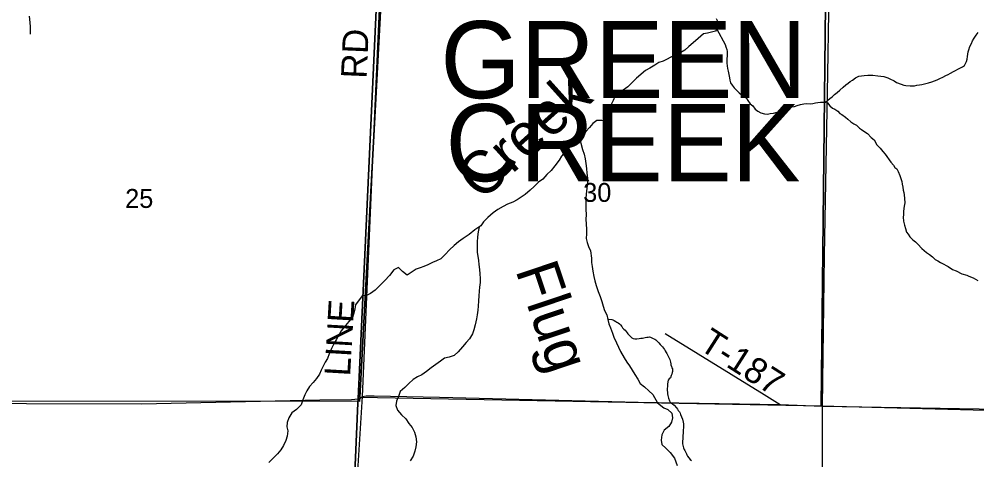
# Model space of a CAD drawing. Extents: x 36.7 to 70.7, y 0 to 22.
# Drawn here: x 40.424 to 42.544, y 14.842 to 15.816 of the extents above; entities that cross this region are included whole.
import ezdxf

# ---------------------------------------------------------------- set-up
doc = ezdxf.new("R2010")
doc.units = 0
for name, color, linetype in [('GM_X_County_Road', 7, 'Continuous'), ('GM_X_County_Road_Text', 7, 'Continuous'), ('GM_X_Minor_River', 7, 'Continuous'), ('GM_X_Minor_River_Text', 7, 'Continuous'), ('GM_X_Section', 7, 'Continuous'), ('GM_X_Section_Text', 7, 'Continuous'), ('GM_X_State_Route', 7, 'Continuous'), ('GM_X_Township_Road', 7, 'Continuous'), ('GM_X_Township_Road_Text', 7, 'Continuous'), ('GM_X_Township_Text', 7, 'Continuous')]:
    doc.layers.add(name, color=color, linetype=linetype)

msp = doc.modelspace()

# ---------------------------------------------------------------- linework, layer by layer
at = {"layer": 'GM_X_County_Road'}
for p, q in [((41.1529, 14.4774), (41.1844, 14.9819)), ((42.202, 14.9604), (42.7218, 14.9518))]:
    msp.add_line(p, q, dxfattribs=at)
for points in [[(41.1844, 14.9819), (41.2095, 15.5574), (41.2295, 16.0217), (41.2394, 16.377)], [(39.1004, 14.9709), (39.3903, 14.9674), (39.7009, 14.9673), (39.866, 14.9673), (40.1853, 14.9672), (40.6951, 14.9659), (41.0895, 14.9744), (41.1597, 14.9749), (41.1747, 14.9764), (41.1765, 14.9766), (41.1844, 14.9819)], [(41.1844, 14.9819), (41.1925, 14.983), (41.2101, 14.9829), (41.3544, 14.98), (41.7944, 14.9695), (42.1083, 14.9642), (42.202, 14.9604)]]:
    msp.add_lwpolyline(points, dxfattribs=at)
at = {"layer": 'GM_X_Minor_River'}
for points in [[(40.4461, 15.8224), (40.4479, 15.8083), (40.4489, 15.7989), (40.4487, 15.7825)], [(41.9671, 15.8174), (41.971, 15.8086), (41.9692, 15.7965), (41.9687, 15.7938), (41.9652, 15.7892)], [(41.9687, 15.7938), (41.987, 15.7599), (41.9884, 15.7549), (41.9903, 15.7488), (41.991, 15.7443), (41.9907, 15.7185), (41.991, 15.7128), (41.9917, 15.7067), (41.9931, 15.701), (41.9949, 15.6937), (41.9964, 15.6861), (41.9974, 15.6808), (41.9989, 15.6751), (42.0026, 15.6697), (42.0071, 15.664), (42.0124, 15.6582), (42.018, 15.6529), (42.0225, 15.6494), (42.0274, 15.6463), (42.033, 15.6417), (42.0368, 15.636), (42.042, 15.6287), (42.048, 15.6241), (42.0532, 15.6172), (42.0589, 15.6126), (42.066, 15.6087), (42.074, 15.6063), (42.0804, 15.6059), (42.0861, 15.6073), (42.0937, 15.6084), (42.1021, 15.6102), (42.1089, 15.612), (42.1143, 15.6146), (42.1196, 15.6168), (42.1249, 15.6183), (42.1333, 15.622), (42.1406, 15.6231), (42.1463, 15.6253), (42.1535, 15.6271), (42.1607, 15.6286), (42.1676, 15.6296), (42.1751, 15.6284), (42.1812, 15.6295), (42.1865, 15.6306), (42.1919, 15.6313), (42.1975, 15.632), (42.2036, 15.6323), (42.2086, 15.6326), (42.2139, 15.6367), (42.2185, 15.6408), (42.2235, 15.6438), (42.2288, 15.6491), (42.2346, 15.6536), (42.2403, 15.6588), (42.248, 15.6656), (42.2541, 15.6708), (42.2587, 15.6742), (42.2637, 15.6779), (42.2683, 15.6813), (42.2752, 15.6858), (42.2828, 15.6899), (42.2942, 15.6916), (42.3025, 15.6923), (42.3079, 15.6923), (42.3139, 15.6918), (42.3245, 15.6909), (42.3378, 15.6889), (42.3465, 15.6858), (42.351, 15.6838), (42.3608, 15.6795), (42.3661, 15.6757), (42.3763, 15.6725), (42.3823, 15.6702), (42.3869, 15.669), (42.396, 15.6682), (42.4009, 15.6681), (42.4062, 15.6688), (42.4112, 15.6699), (42.4169, 15.671), (42.4218, 15.6717), (42.4313, 15.6738), (42.4366, 15.6749), (42.4442, 15.6771), (42.4503, 15.6793), (42.456, 15.6816), (42.4621, 15.6845), (42.4686, 15.6875), (42.4755, 15.6912), (42.4805, 15.6934), (42.4858, 15.6964), (42.4919, 15.6998), (42.4965, 15.7024), (42.5015, 15.705), (42.506, 15.7072), (42.5118, 15.7106), (42.5167, 15.7135), (42.521, 15.7219), (42.5222, 15.7272), (42.5234, 15.7332), (42.5238, 15.7381), (42.5246, 15.7435)], [(41.9652, 15.7892), (41.9565, 15.7868), (41.9478, 15.785), (41.9387, 15.7836), (41.9268, 15.7734), (41.9157, 15.7633), (41.9065, 15.7554), (41.8977, 15.7476), (41.8885, 15.742), (41.8798, 15.739), (41.8584, 15.7271), (41.8496, 15.723), (41.8401, 15.7201), (41.8309, 15.7145), (41.8199, 15.7078), (41.8103, 15.7026), (41.7904, 15.6853), (41.7812, 15.6759), (41.7716, 15.6665), (41.7586, 15.6576), (41.7498, 15.6539), (41.7425, 15.6448), (41.7386, 15.6362), (41.7344, 15.6271), (41.732, 15.6169), (41.7317, 15.5971), (41.7222, 15.5904), (41.7135, 15.5916), (41.7029, 15.5921), (41.6937, 15.5854), (41.6864, 15.5764), (41.6787, 15.5673), (41.6706, 15.5572), (41.6614, 15.5501), (41.6507, 15.5422), (41.6407, 15.5332), (41.6338, 15.5242), (41.6242, 15.5133), (41.6195, 15.5038), (41.6099, 15.4914), (41.6015, 15.4816), (41.5922, 15.4722), (41.583, 15.4625), (41.5738, 15.4553), (41.5643, 15.446), (41.5551, 15.4381), (41.5443, 15.4279), (41.5355, 15.4227), (41.5267, 15.4164), (41.5168, 15.4115), (41.5054, 15.4067), (41.4951, 15.4015), (41.4833, 15.3948), (41.4733, 15.3881), (41.4614, 15.3776), (41.4519, 15.3682), (41.4461, 15.3588), (41.4327, 15.3502), (41.4204, 15.3401), (41.4067, 15.3311), (41.3967, 15.3236), (41.3872, 15.3154), (41.3768, 15.3056), (41.3672, 15.2959)], [(42.5246, 15.7435), (42.5258, 15.748), (42.5282, 15.7556), (42.5317, 15.762), (42.534, 15.7676), (42.5379, 15.7741), (42.5425, 15.7805), (42.5468, 15.7865)], [(42.2099, 15.6336), (42.2135, 15.631), (42.2187, 15.6241), (42.2247, 15.6191), (42.2292, 15.6172), (42.236, 15.6122), (42.2405, 15.6072), (42.245, 15.6049), (42.2529, 15.5991), (42.2582, 15.5949), (42.265, 15.5891), (42.2717, 15.5841), (42.2774, 15.5814), (42.2838, 15.5752), (42.2883, 15.5721), (42.2939, 15.5679), (42.3018, 15.5629), (42.3101, 15.5541), (42.3169, 15.5494), (42.3228, 15.538), (42.3299, 15.5307), (42.3355, 15.5234), (42.3411, 15.5177), (42.3445, 15.5119), (42.3497, 15.505), (42.3535, 15.5001), (42.3591, 15.4932), (42.3621, 15.4882), (42.3666, 15.4847), (42.3695, 15.4794), (42.3736, 15.4699), (42.3758, 15.4638), (42.378, 15.4573), (42.3787, 15.4508), (42.3801, 15.4447), (42.3808, 15.4375), (42.3823, 15.4326), (42.383, 15.4276), (42.384, 15.4193), (42.3843, 15.4101), (42.3827, 15.4022), (42.3818, 15.3912), (42.3813, 15.3836), (42.3809, 15.3779), (42.3812, 15.3692), (42.3837, 15.3608), (42.3863, 15.3528), (42.3885, 15.3452), (42.3922, 15.3406), (42.3956, 15.3345), (42.402, 15.3279), (42.408, 15.3233), (42.4136, 15.3183), (42.4218, 15.3088), (42.4327, 15.2999), (42.4391, 15.2953), (42.4459, 15.2907), (42.4515, 15.2849), (42.4572, 15.2814), (42.4636, 15.2779), (42.4711, 15.2741), (42.4757, 15.2714), (42.4802, 15.269), (42.4903, 15.2625), (42.4979, 15.2593), (42.5103, 15.2531), (42.5217, 15.2496), (42.5262, 15.248), (42.5357, 15.2441), (42.5462, 15.2383)], [(41.6675, 15.5547), (41.6652, 15.5508), (41.6674, 15.5416), (41.6714, 15.5279), (41.6747, 15.5176), (41.6768, 15.507), (41.6786, 15.4967), (41.68, 15.4861), (41.6807, 15.4754), (41.682, 15.464), (41.682, 15.4553), (41.6807, 15.4424), (41.6794, 15.4291), (41.6785, 15.4193), (41.6784, 15.4056), (41.6786, 15.395), (41.6789, 15.384), (41.6787, 15.373), (41.6794, 15.3631), (41.68, 15.3509), (41.6799, 15.3414), (41.6794, 15.3308), (41.6816, 15.3221), (41.6845, 15.3133), (41.689, 15.3038), (41.6907, 15.2878), (41.6913, 15.2779), (41.6923, 15.2688), (41.6938, 15.2589), (41.6959, 15.2468), (41.6981, 15.2376), (41.7014, 15.227), (41.7054, 15.214), (41.7098, 15.2026), (41.7139, 15.1919), (41.7168, 15.1812), (41.7197, 15.1717), (41.7249, 15.1625), (41.7271, 15.1523), (41.7296, 15.1424), (41.7329, 15.1336), (41.7377, 15.1214), (41.7406, 15.1126), (41.7466, 15.1004), (41.7506, 15.0905), (41.7551, 15.081), (41.7629, 15.0676), (41.7688, 15.058), (41.7748, 15.0493), (41.7808, 15.0397), (41.7871, 15.0301), (41.7934, 15.0198), (41.799, 15.0103), (41.8081, 15.0033), (41.8178, 14.9941), (41.8264, 14.9861), (41.8372, 14.9681), (41.8511, 14.9569), (41.8598, 14.953), (41.8685, 14.9446), (41.8702, 14.9343), (41.8682, 14.9249), (41.862, 14.9151), (41.8517, 14.9076), (41.8463, 14.8974), (41.8454, 14.8856), (41.8468, 14.8757), (41.8554, 14.8677), (41.8648, 14.8577), (41.8745, 14.8458), (41.8808, 14.8294)], [(41.4425, 15.3565), (41.4398, 15.3459), (41.4386, 15.3349), (41.4381, 15.3228), (41.4379, 15.311), (41.4382, 15.3004), (41.4392, 15.2917), (41.4406, 15.2822), (41.4417, 15.2734), (41.4431, 15.2624), (41.4441, 15.2529), (41.4447, 15.2423), (41.4443, 15.2335), (41.4434, 15.2233), (41.4425, 15.2146), (41.4416, 15.2043), (41.4408, 15.1933), (41.4399, 15.1812), (41.4394, 15.1725), (41.4381, 15.1622), (41.4361, 15.1531), (41.4333, 15.1399), (41.4306, 15.1293), (41.4278, 15.1206), (41.4212, 15.1096), (41.4139, 15.101), (41.4055, 15.0912), (41.3959, 15.0807), (41.3867, 15.0724), (41.376, 15.0688), (41.3657, 15.0662), (41.3569, 15.0599), (41.3466, 15.0524), (41.3363, 15.0453), (41.3256, 15.037), (41.3156, 15.0299), (41.3057, 15.0251), (41.2962, 15.0195), (41.2866, 15.0105), (41.2781, 15.0019), (41.2678, 14.9925), (41.2643, 14.9838), (41.2596, 14.9717), (41.258, 14.9622), (41.2616, 14.9519), (41.2706, 14.9416), (41.28, 14.9324), (41.2867, 14.9221), (41.2938, 14.9129), (41.299, 14.9029), (41.3023, 14.8923), (41.3037, 14.8816), (41.3021, 14.8706), (41.2997, 14.8608), (41.2961, 14.8498), (41.2896, 14.8396)], [(41.3672, 15.2959), (41.3576, 15.2857), (41.3481, 15.2813), (41.3389, 15.2776), (41.329, 15.2731), (41.3202, 15.269), (41.3115, 15.2665), (41.3027, 15.2635), (41.2939, 15.2572), (41.2829, 15.2497), (41.2723, 15.2582), (41.2637, 15.2666), (41.2534, 15.2614), (41.2438, 15.2494), (41.2338, 15.2381), (41.223, 15.2276), (41.2119, 15.2171), (41.202, 15.2096), (41.1932, 15.2047), (41.1833, 15.2041), (41.1687, 15.1845), (41.1671, 15.1754), (41.1651, 15.1659), (41.1619, 15.1572), (41.1542, 15.1478), (41.1462, 15.1388), (41.1366, 15.1271), (41.1323, 15.1185), (41.1261, 15.1071), (41.1207, 15.0981), (41.1156, 15.0875), (41.1106, 15.0758), (41.1063, 15.066), (41.1013, 15.0573), (41.0927, 15.0399), (41.0888, 15.0312), (41.0823, 15.0218), (41.075, 15.0128), (41.0669, 15.0041), (41.0607, 14.9943), (41.0561, 14.9857), (41.0518, 14.9747), (41.0482, 14.963), (41.0382, 14.9532), (41.0275, 14.9454), (41.0213, 14.9348), (41.0171, 14.9246), (41.0169, 14.9147), (41.0187, 14.906), (41.0175, 14.8942), (41.0143, 14.8844), (41.0093, 14.8738), (41.0031, 14.8636), (40.9962, 14.855), (40.9866, 14.8452), (40.9766, 14.8358)], [(41.7295, 15.1524), (41.7356, 15.1522), (41.7382, 15.1511), (41.7412, 15.1499), (41.7446, 15.1479), (41.7472, 15.1463), (41.7498, 15.1444), (41.7528, 15.1424), (41.7554, 15.1401), (41.758, 15.1366), (41.7598, 15.1339), (41.7628, 15.1308), (41.7657, 15.1281), (41.7676, 15.1254), (41.7698, 15.1227), (41.7716, 15.12), (41.7746, 15.1173), (41.7772, 15.1142), (41.7801, 15.1115), (41.7831, 15.1099), (41.7869, 15.1091), (41.7911, 15.1094), (41.7964, 15.1101), (41.8002, 15.1104), (41.804, 15.111), (41.8101, 15.1124), (41.8135, 15.1131), (41.8161, 15.1131), (41.8192, 15.1134), (41.8218, 15.113), (41.8244, 15.1118), (41.8278, 15.1102), (41.8308, 15.1086), (41.8334, 15.1067), (41.8368, 15.1032), (41.8397, 15.1005), (41.8431, 15.0966), (41.8456, 15.0939), (41.8482, 15.0916), (41.8501, 15.0885), (41.8527, 15.0858), (41.8541, 15.0827), (41.8563, 15.0793), (41.8578, 15.0766), (41.8632, 15.0662), (41.8643, 15.0632), (41.865, 15.0605), (41.8657, 15.0575), (41.8664, 15.054), (41.8667, 15.0514), (41.8682, 15.0479), (41.8689, 15.0453), (41.8699, 15.0426), (41.8699, 15.0399), (41.8702, 15.0373), (41.8698, 15.0346), (41.8689, 15.0308), (41.8674, 15.0282), (41.8657, 15.0229), (41.8631, 15.0211), (41.8607, 15.0177), (41.8599, 15.0143), (41.859, 15.009), (41.8589, 15.0033), (41.8585, 15.0003), (41.8584, 14.995), (41.859, 14.9912), (41.8593, 14.9878), (41.86, 14.9843), (41.8603, 14.9809), (41.8614, 14.9783), (41.8636, 14.9721), (41.8654, 14.9694), (41.868, 14.9671), (41.8706, 14.9652), (41.8736, 14.9625), (41.8791, 14.9567), (41.881, 14.954), (41.8828, 14.9505), (41.8854, 14.9478), (41.8872, 14.9447), (41.8883, 14.9421), (41.8926, 14.9317), (41.894, 14.9249), (41.8943, 14.9214), (41.8946, 14.9176), (41.8945, 14.9116), (41.894, 14.9089), (41.8936, 14.9055), (41.8935, 14.8998), (41.893, 14.8964), (41.893, 14.8938), (41.8926, 14.8775), (41.8929, 14.8744), (41.894, 14.871), (41.8947, 14.8683), (41.8962, 14.8649), (41.8972, 14.8622), (41.9009, 14.8553), (41.9016, 14.8526), (41.9038, 14.8496)], [(41.9038, 14.8496), (41.9064, 14.8465), (41.9097, 14.8426), (41.9123, 14.8403)]]:
    msp.add_lwpolyline(points, dxfattribs=at)
at = {"layer": 'GM_X_Section'}
for points in [[(42.2098, 15.9172), (42.199, 14.9604), (41.1785, 14.9796), (41.2265, 15.8756), (41.2283, 15.9252)], [(41.2265, 15.8756), (41.1785, 14.9796), (41.1776, 14.9705), (40.1892, 14.9717), (40.1834, 15.4299), (40.1588, 15.7484), (40.1632, 15.9076)], [(43.2232, 15.9056), (43.2077, 14.934), (42.199, 14.9604), (42.2098, 15.9172)]]:
    msp.add_lwpolyline(points, close=True, dxfattribs=at)
at = {"layer": 'GM_X_State_Route'}
msp.add_lwpolyline([(42.2026, 14.6407), (42.202, 14.9604), (42.2067, 15.2937), (42.2144, 15.6947), (42.2208, 16.1022)], dxfattribs=at)
at = {"layer": 'GM_X_Township_Road'}
for points in [[(41.1522, 14.4699), (41.174, 14.9671), (41.1745, 14.977), (41.2392, 16.3776), (41.2409, 16.4152), (41.2499, 16.8815), (41.2661, 17.5372), (41.3022, 18.3874), (41.3025, 18.3936), (41.3037, 18.4227), (41.344, 19.4017), (41.3441, 19.4051), (41.3623, 19.8162), (40.8614, 19.8261), (40.8514, 19.8263), (40.7997, 19.8273), (40.7924, 19.8275), (40.7387, 19.8285), (40.7272, 19.8287), (40.1721, 19.8397)], [(41.2661, 17.5372), (41.2499, 16.8815), (41.2409, 16.4152), (41.2392, 16.3776), (41.1745, 14.977), (41.174, 14.9671), (41.1522, 14.4699)], [(41.8542, 15.1208), (42.0735, 14.986), (42.1083, 14.9642)]]:
    msp.add_lwpolyline(points, dxfattribs=at)

# ---------------------------------------------------------------- texts
at = {"layer": 'GM_X_County_Road_Text'}
for s, rotation, p in [('RD', 87.5314, (41.1932, 15.6836)), ('LINE', 86.6697, (41.1565, 15.0256))]:
    msp.add_text(s, height=0.05682, rotation=rotation, dxfattribs=at).set_placement(p)
at = {"layer": 'GM_X_Minor_River_Text'}
for s, height, rotation, p in [('Creek', 0.09474, 41.9879, (41.4469, 15.4111)), ('Flug', 0.09476, 288.5487, (41.522, 15.2615))]:
    msp.add_text(s, height=height, rotation=rotation, dxfattribs=at).set_placement(p)
at = {"layer": 'GM_X_Section_Text'}
for s, p in [('30', (41.6726, 15.4119)), ('25', (40.6588, 15.3986))]:
    msp.add_text(s, height=0.04186, rotation=0, dxfattribs=at).set_placement(p)
at = {"layer": 'GM_X_Township_Road_Text'}
msp.add_text('T-187', height=0.05682, rotation=327.3955, dxfattribs=at).set_placement((41.9261, 15.088))
at = {"layer": 'GM_X_Township_Text'}
for s, p in [('GREEN', (41.3566, 15.6412)), ('CREEK', (41.3678, 15.4577))]:
    msp.add_text(s, height=0.17045, rotation=0, dxfattribs=at).set_placement(p)

doc.saveas('drawing.dxf')
